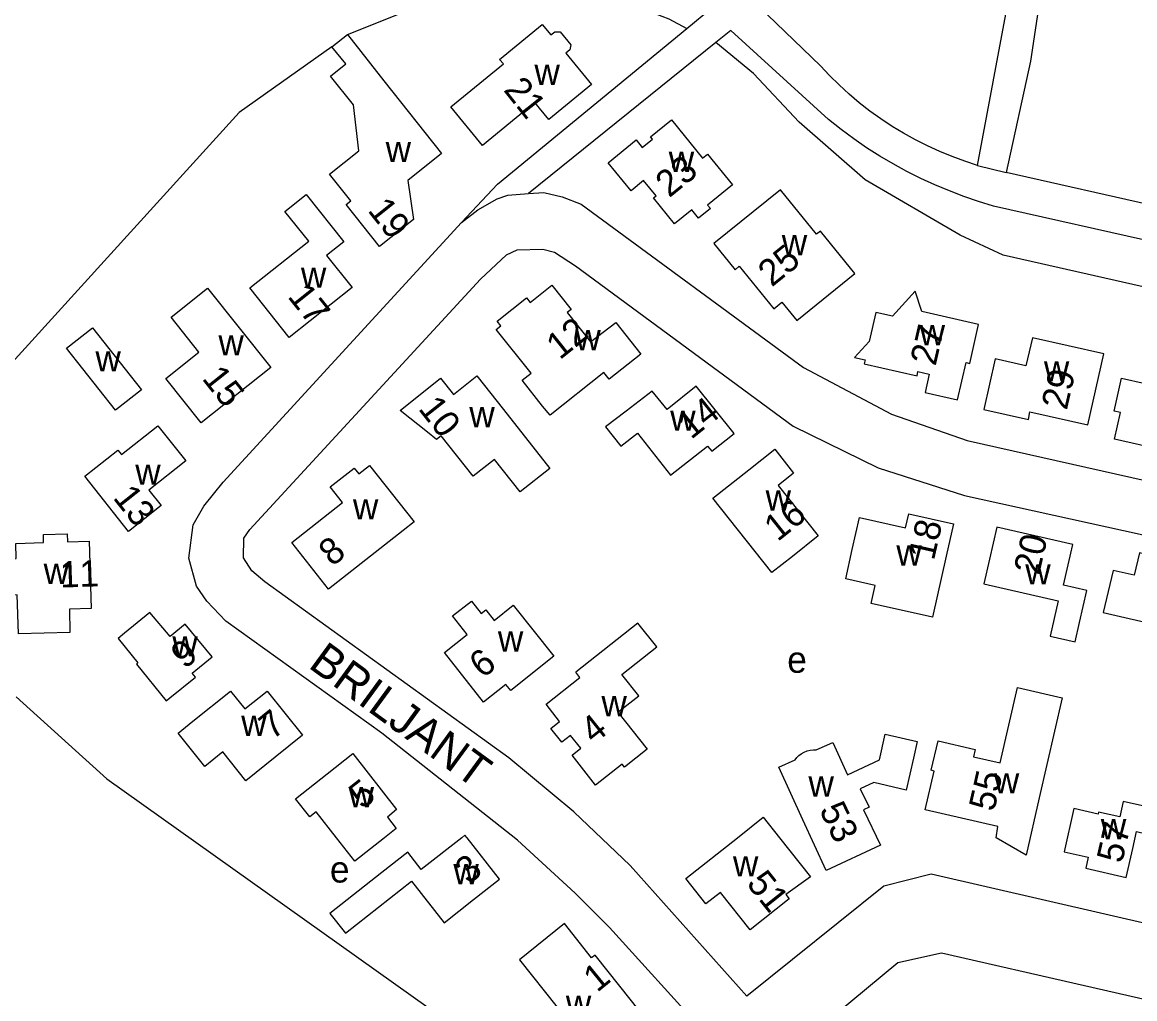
# Model space of a CAD drawing. Extents: x 159441 to 162086, y 388175 to 389787.
# Drawn here: x 160042 to 160211, y 388725.5 to 388873.9 of the extents above; entities that cross this region are included whole.
import ezdxf

# ---------------------------------------------------------------- set-up
doc = ezdxf.new("R2010")
doc.units = 0
for name, color, linetype in [('BLT_Basislijn', 7, 'Continuous'), ('BLT_Bebouwing', 7, 'Continuous'), ('BLT_Centroide', 7, 'Continuous'), ('BLT_Huisnummer', 7, 'Continuous'), ('BLT_Straatnaam', 7, 'Continuous')]:
    doc.layers.add(name, color=color, linetype=linetype)

msp = doc.modelspace()

# ---------------------------------------------------------------- linework, layer by layer
at = {"layer": 'BLT_Basislijn'}
for p, q in [((160163.23, 388867.23), (160150.84, 388879.16)), ((160187.09, 388852.12), (160191.81, 388877.57)), ((160142.94, 388872.91), (160146.74, 388876.03)), ((160149.61, 388872.62), (160147.33, 388870.78)), ((160164.44, 388859.07), (160149.61, 388872.62)), ((160147.33, 388870.78), (160118.89, 388847.84)), ((160187.09, 388852.12), (160191.44, 388851.02)), ((160360.88, 388812.74), (160191.44, 388851.02)), ((160346.93, 388810.56), (160189.5, 388845.95)), ((160115.55, 388838.53), (160117.14, 388839.28)), ((160117.14, 388839.28), (160121.07, 388839.39)), ((160121.07, 388839.39), (160122.81, 388838.92)), ((160111.6, 388834.85), (160115.55, 388838.53)), ((160122.81, 388838.92), (160125.99, 388836.85)), ((160125.99, 388836.85), (160159.06, 388812.49)), ((160076.55, 388796.83), (160111.6, 388834.85)), ((160159.06, 388812.49), (160171.97, 388806.18)), ((160171.97, 388806.18), (160185.1, 388801.99)), ((160185.1, 388801.99), (160246.65, 388788.38)), ((160075.64, 388795.49), (160076.55, 388796.83)), ((160075.56, 388792.53), (160075.64, 388795.49)), ((160076.87, 388790.53), (160075.56, 388792.53)), ((160078.84, 388788.84), (160076.87, 388790.53)), ((160115.87, 388762.13), (160078.84, 388788.84)), ((160125.73, 388753.92), (160115.87, 388762.13)), ((160134.33, 388745.8), (160125.73, 388753.92)), ((160152.02, 388725.93), (160134.33, 388745.8)), ((160180.01, 388744.45), (160172.85, 388742.62)), ((160234.52, 388731.91), (160180.01, 388744.45)), ((160172.85, 388742.62), (160152.02, 388725.93))]:
    msp.add_line(p, q, dxfattribs=at)
for points in [[(160218.9, 388909.49), (160213.34, 388904.91), (160206.65, 388898.54), (160202.29, 388892.55), (160198.36, 388884.11), (160196.72, 388878.8), (160195.13, 388867.95), (160191.44, 388851.02)], [(160091.36, 388872), (160103.18, 388876.69), (160111.74, 388878.51), (160119, 388879.07), (160125.96, 388878.73), (160132.75, 388877.29), (160140.2, 388874.39), (160142.94, 388872.91)], [(160108.7, 388843.42), (160114.14, 388849.26), (160142.94, 388872.91)], [(160089.02, 388870.15), (160074.94, 388860.17), (160014.9, 388794.07)], [(160345.36, 388803.54), (160190.94, 388838.49), (160184.45, 388841.51), (160169.98, 388849.95), (160159.97, 388858.67), (160153.03, 388866.08), (160147.33, 388870.78)], [(160187.09, 388852.12), (160185.14, 388852.75), (160183.22, 388853.45), (160181.33, 388854.23), (160179.46, 388855.08), (160177.64, 388856), (160175.85, 388856.99), (160174.1, 388858.05), (160172.39, 388859.18), (160170.73, 388860.38), (160169.11, 388861.64), (160167.55, 388862.96), (160166.04, 388864.35), (160164.58, 388865.79), (160163.23, 388867.23)], [(160189.5, 388845.95), (160187.24, 388846.64), (160185, 388847.41), (160182.79, 388848.25), (160180.61, 388849.16), (160178.46, 388850.15), (160176.34, 388851.21), (160174.26, 388852.34), (160172.22, 388853.54), (160170.23, 388854.81), (160168.27, 388856.15), (160166.37, 388857.55), (160164.44, 388859.07)], [(160108.7, 388843.42), (160111.15, 388845.37), (160114.12, 388847.06), (160115.71, 388847.62), (160118.89, 388847.84)], [(160118.89, 388847.84), (160121.21, 388847.99), (160123.99, 388847.35), (160126.85, 388846.24), (160160.65, 388821.41), (160174.02, 388814.31), (160185.49, 388810.35), (160339.15, 388775.78)], [(160128.08, 388707.15), (160129.69, 388708.17), (160145.39, 388720.67), (160131.15, 388736.37), (160125.98, 388741.58), (160117.21, 388749.62), (160096.61, 388765.86), (160072.89, 388782.89), (160069.99, 388785.94), (160068.43, 388788.2), (160067.27, 388792.47), (160067.96, 388797.53), (160069.56, 388800.35), (160072.51, 388804), (160108.7, 388843.42)], [(160041.05, 388771.4), (160054.83, 388758.93), (160120.14, 388712.44), (160128.08, 388707.15)], [(160114.51, 388683.05), (160165.44, 388723.15), (160174.96, 388731.02), (160181.6, 388732.52), (160225.05, 388722.57), (160225.4, 388722.49)]]:
    msp.add_lwpolyline(points, dxfattribs=at)
at = {"layer": 'BLT_Bebouwing'}
for p, q in [((160089.02, 388870.15), (160091.36, 388872)), ((160091.36, 388872), (160096.91, 388864.98)), ((160135.49, 388782.6), (160126.07, 388775.13)), ((160138.36, 388778.98), (160135.49, 388782.6)), ((160133.06, 388774.77), (160138.36, 388778.98)), ((160135.61, 388771.56), (160133.06, 388774.77)), ((160132.43, 388769.05), (160135.61, 388771.56))]:
    msp.add_line(p, q, dxfattribs=at)
for points in [[(160120.97, 388873.54), (160122.28, 388871.93), (160122.89, 388872.43), (160123.66, 388872.41), (160125.29, 388870.43), (160125.15, 388869.67), (160124.54, 388869.17), (160128.46, 388864.39), (160121.95, 388859.1), (160119.85, 388861.69), (160111.9, 388855.13), (160107.09, 388861), (160115.05, 388867.53), (160114.48, 388868.22), (160120.97, 388873.54)], [(160096.91, 388864.98), (160105.67, 388853.9), (160100.52, 388849.8), (160101.39, 388843.9), (160096.23, 388839.82), (160091.17, 388846.2), (160091.87, 388846.75), (160088.66, 388850.79), (160093.11, 388854.31), (160092.27, 388861.3), (160088.8, 388865.69), (160091.11, 388867.52), (160089.02, 388870.15)], [(160135.22, 388855.98), (160136.14, 388854.84), (160137.7, 388856.1), (160137.41, 388856.45), (160140.57, 388859.02), (160145.29, 388853.22), (160146.04, 388853.83), (160149.86, 388849.16), (160146.07, 388846.07), (160146.49, 388845.56), (160144.71, 388844.11), (160143.67, 388845.38), (160141.06, 388843.25), (160137.88, 388847.17), (160138.27, 388847.49), (160136.36, 388849.83), (160134.46, 388848.26), (160130.96, 388852.51), (160135.22, 388855.98)], [(160085.1, 388847.69), (160090.8, 388840.49), (160088.21, 388838.43), (160092.07, 388833.57), (160082.5, 388825.99), (160076.54, 388833.52), (160085.48, 388840.6), (160081.88, 388845.14), (160085.1, 388847.69)], [(160147.04, 388840.24), (160150.26, 388836.28), (160150.89, 388836.79), (160156.12, 388830.33), (160157.37, 388831.34), (160159.61, 388828.55), (160168.45, 388835.71), (160163.23, 388842.15), (160162.61, 388841.65), (160157.13, 388848.41), (160147.04, 388840.24)], [(160131.13, 388819.64), (160130.3, 388820.68), (160122.15, 388814.16), (160121.02, 388815.57), (160117.9, 388819.48), (160119.27, 388820.58), (160113.98, 388827.19), (160114.68, 388827.74), (160114.12, 388828.44), (160118.59, 388831.99), (160119.14, 388831.3), (160122.4, 388833.92), (160125.33, 388830.23), (160124.74, 388829.75), (160128.28, 388825.3), (160132.11, 388828.28), (160135.92, 388823.47), (160131.13, 388819.64)], [(160070.13, 388833.46), (160079.73, 388821.42), (160069.17, 388813.01), (160063.81, 388819.74), (160068.82, 388823.73), (160064.58, 388829.05), (160070.13, 388833.46)], [(160170, 388822.59), (160169.86, 388821.99), (160177.88, 388820.16), (160178.02, 388820.79), (160179.74, 388820.41), (160179.13, 388817.63), (160184.04, 388816.52), (160185.34, 388822.18), (160185.88, 388822.05), (160187.2, 388827.94), (160178.61, 388829.91), (160177.62, 388833.01), (160174.17, 388829.2), (160171.63, 388829.77), (160170.63, 388825.38), (160168.38, 388822.95), (160170, 388822.59)], [(160194.8, 388813.52), (160195.03, 388814.71), (160203.8, 388812.71), (160206.25, 388823.5), (160195.4, 388825.93), (160194.43, 388821.66), (160189.77, 388822.72), (160188.04, 388815.05), (160194.8, 388813.52)], [(160223.52, 388806.98), (160207.88, 388810.55), (160208.78, 388814.59), (160207.81, 388814.8), (160208.92, 388819.79), (160216.14, 388818.18), (160217.77, 388825.31), (160227.21, 388823.15), (160223.52, 388806.98)], [(160111.01, 388820.16), (160115.05, 388815.03), (160122.12, 388806.1), (160117.6, 388802.52), (160113.7, 388807.45), (160110.48, 388804.9), (160105.6, 388811.04), (160104.91, 388810.49), (160103.51, 388811.6), (160099.37, 388814.9), (160105.51, 388819.8), (160107.5, 388817.34), (160111.01, 388820.16)], [(160146.7, 388808.7), (160150.09, 388811.37), (160144.33, 388818.56), (160139.91, 388815.03), (160137.63, 388817.85), (160133.68, 388814.79), (160130.58, 388812.4), (160132.9, 388809.46), (160135.43, 388811.46), (160140.46, 388805.07), (160146.07, 388809.49), (160146.7, 388808.7)], [(160051.48, 388804.89), (160056.51, 388808.87), (160057.03, 388808.2), (160062.57, 388812.58), (160066.8, 388807.23), (160061.21, 388802.81), (160063.07, 388800.46), (160058.1, 388796.53), (160051.48, 388804.89)], [(160158.96, 388792.73), (160155.84, 388790.26), (160146.86, 388801.56), (160152.35, 388805.9), (160156.27, 388809), (160159.14, 388805.36), (160156.8, 388803.49), (160162.89, 388795.83), (160158.96, 388792.73)], [(160088.51, 388787.77), (160082.93, 388794.82), (160090.63, 388800.93), (160088.76, 388803.29), (160092.38, 388806.14), (160093.08, 388805.25), (160094.73, 388806.55), (160101.48, 388797.99), (160099.83, 388796.68), (160088.51, 388787.77)], [(160182.31, 388792.78), (160180.21, 388783.48), (160170.92, 388785.58), (160171.54, 388788.32), (160167.05, 388789.34), (160168.05, 388793.77), (160169.15, 388798.65), (160176.11, 388797.07), (160176.62, 388799.21), (160183.42, 388797.65), (160182.31, 388792.78)], [(160202.56, 388782.68), (160203.67, 388787.55), (160200.14, 388788.34), (160201.56, 388794.54), (160190.01, 388797.17), (160188.9, 388792.31), (160188.04, 388788.56), (160199.34, 388785.97), (160198.11, 388780.6), (160201.89, 388779.74), (160202.56, 388782.68)], [(160048.83, 388794.94), (160052.12, 388795.03), (160052.43, 388784.82), (160049.15, 388784.71), (160049.22, 388781.15), (160041.4, 388780.96), (160041.23, 388786.91), (160039.62, 388786.86), (160038.02, 388789.56), (160039.46, 388792.37), (160041.07, 388792.41), (160041.01, 388794.71), (160045.22, 388794.83), (160045.18, 388796.03), (160048.8, 388796.14), (160048.83, 388794.94)], [(160223.08, 388782.73), (160224.18, 388787.61), (160220.78, 388788.38), (160221.15, 388790.08), (160216.23, 388791.23), (160216.39, 388792.16), (160211.65, 388793.28), (160210.87, 388789.87), (160207.65, 388790.61), (160206.17, 388784.19), (160215.17, 388782.14), (160214.96, 388781.22), (160218.67, 388780.38), (160218.45, 388779.41), (160222.14, 388778.58), (160223.08, 388782.73)], [(160115.45, 388773.28), (160112.04, 388770.59), (160106.09, 388778.11), (160109.57, 388780.89), (160107.33, 388783.69), (160110.19, 388785.95), (160111.67, 388784.06), (160112.38, 388784.62), (160113.66, 388783.01), (160116.54, 388785.31), (160122.7, 388777.59), (160116.17, 388772.38), (160115.45, 388773.28)], [(160064.39, 388771.23), (160068.27, 388774.39), (160067.78, 388774.99), (160070.81, 388777.46), (160066.73, 388782.42), (160064.43, 388780.55), (160061.37, 388784.23), (160057.5, 388781.07), (160056.52, 388780.27), (160059.54, 388776.56), (160059.31, 388776.37), (160063.86, 388770.8), (160064.39, 388771.23)], [(160136.89, 388763.43), (160133.45, 388760.7), (160133.08, 388761.17), (160129.07, 388757.99), (160125.5, 388762.55), (160126.82, 388763.58), (160125.24, 388765.54), (160123.92, 388764.51), (160122.24, 388766.6), (160123.59, 388767.67), (160121.53, 388770.27), (160126.69, 388774.35), (160126.07, 388775.13)], [(160084.54, 388765.55), (160080.39, 388762.23), (160075.94, 388758.66), (160072.45, 388763.02), (160069.73, 388760.84), (160065.68, 388765.9), (160067.89, 388767.69), (160073.59, 388772.27), (160075.78, 388769.58), (160079.2, 388772.27), (160084.54, 388765.55)], [(160196.45, 388756.04), (160194.45, 388747.37), (160189.9, 388750), (160190.16, 388751.71), (160179.14, 388754.23), (160180.46, 388760.11), (160180.05, 388760.24), (160181.08, 388764.7), (160186.72, 388763.4), (160186.46, 388762.28), (160190.51, 388761.35), (160193.14, 388772.82), (160199.95, 388771.25), (160196.45, 388756.04)], [(160132.43, 388769.05), (160136.89, 388763.43)], [(160164.1, 388745.03), (160160.56, 388752.7), (160156.88, 388760.69), (160159.37, 388761.85), (160159.63, 388762.17), (160159.93, 388762.47), (160160.29, 388762.75), (160160.74, 388763.01), (160161.21, 388763.19), (160161.66, 388763.3), (160162.16, 388763.34), (160162.57, 388763.33), (160165.07, 388764.48), (160167.34, 388759.57), (160172.16, 388761.83), (160173.06, 388765.73), (160177.92, 388764.61), (160177.34, 388762.07), (160176.21, 388757.2), (160171.34, 388758.38), (160169.27, 388757.41), (160170.6, 388754.65), (160169.75, 388754.24), (160172.35, 388748.89), (160164.1, 388745.03)], [(160096.98, 388750), (160094.86, 388748.32), (160092.5, 388746.46), (160089.7, 388750), (160086.6, 388753.93), (160085.66, 388753.18), (160083.5, 388755.92), (160088.28, 388759.7), (160092.21, 388762.8), (160098.84, 388754.27), (160097.43, 388753.12), (160098.78, 388751.42), (160096.98, 388750)], [(160215.04, 388754.16), (160209.21, 388755.5), (160208.68, 388753.17), (160205.47, 388753.9), (160205.4, 388753.59), (160201.71, 388754.43), (160200.21, 388747.86), (160203.9, 388747.02), (160203.52, 388745.37), (160209.67, 388743.98), (160210.66, 388748.37), (160211.24, 388750.93), (160214.17, 388750.24), (160215.04, 388754.16)], [(160156.98, 388750), (160161.68, 388744.06), (160157.95, 388741.39), (160158.45, 388740.72), (160152.55, 388736.02), (160148.01, 388741.69), (160145.82, 388739.97), (160142.78, 388743.82), (160150.59, 388750), (160154.52, 388753.11), (160156.98, 388750)], [(160110.53, 388740.62), (160114.46, 388743.71), (160109.53, 388750), (160109.22, 388750.39), (160108.72, 388750), (160102.56, 388745.18), (160100.53, 388747.81), (160096.6, 388744.72), (160088.7, 388738.5), (160091.07, 388735.5), (160101.09, 388743.39), (160106.04, 388737.09), (160110.53, 388740.62)], [(160128.07, 388716.58), (160133.12, 388720.58), (160136.22, 388723.05), (160134.52, 388725.21), (160129.01, 388732.15), (160128.46, 388731.75), (160124.34, 388736.96), (160117.49, 388731.46), (160123.24, 388724.24), (160121.07, 388722.53), (160123.76, 388719.14), (160125.15, 388720.24), (160128.07, 388716.58)]]:
    msp.add_lwpolyline(points, dxfattribs=at)
msp.add_lwpolyline([(160052.63, 388827.44), (160060.07, 388818.03), (160056.15, 388814.93), (160048.7, 388824.34)], close=True, dxfattribs=at)

# ---------------------------------------------------------------- texts
at = {"layer": 'BLT_Centroide'}
for s, p in [('w', (160119.77, 388864.34)), ('w', (160097.17, 388852.62)), ('w', (160140.17, 388851.12)), ('w', (160157.34, 388838.47)), ('w', (160084.3, 388833.53)), ('w', (160178.27, 388824.78)), ('w', (160071.77, 388823.25)), ('w', (160125.98, 388824.03)), ('w', (160053.09, 388820.82)), ('w', (160197.15, 388819.31)), ('w', (160109.88, 388812.34)), ('w', (160140.39, 388811.81)), ('w', (160059.14, 388803.61)), ('w', (160154.88, 388799.69)), ('w', (160092.2, 388798.34)), ('w', (160174.74, 388791.34)), ('w', (160045.22, 388788.55)), ('w', (160194.32, 388788.47)), ('w', (160064.77, 388777.53)), ('w', (160114.22, 388778.28)), ('e', (160158.17, 388775.05)), ('w', (160129.95, 388768.45)), ('w', (160075.23, 388765.47)), ('w', (160189.55, 388756.72)), ('w', (160161.39, 388756.23)), ('w', (160091.54, 388754.62)), ('w', (160205.8, 388749.75)), ('e', (160088.71, 388743.19)), ('w', (160107.46, 388742.94)), ('w', (160149.92, 388744.12)), ('w', (160124.54, 388722.95))]:
    msp.add_text(s, height=4, dxfattribs=at).set_placement(p)
at = {"layer": 'BLT_Huisnummer'}
for s, rotation, p in [('21', 308.5267, (160114.97, 388863.54)), ('23', 39.1153, (160140.24, 388847.11)), ('19', 308.5267, (160094.33, 388845.25)), ('25', 39.015, (160155.81, 388833.55)), ('17', 308.5267, (160082.17, 388832.17)), ('12', 38.5008, (160123.61, 388822.49)), ('27', 77.0623, (160180.69, 388821.54)), ('15', 308.5267, (160069.16, 388819.72)), ('29', 77.1478, (160200.62, 388814.83)), ('10', 308.2228, (160102.02, 388815.14)), ('14', 38.5008, (160143.56, 388810.4)), ('13', 308.3527, (160055.64, 388801.61)), ('16', 38.5008, (160156.7, 388794.88)), ('18', 77.2336, (160180.44, 388791.99)), ('8', 38.6598, (160089.05, 388791.09)), ('20', 77.2336, (160196.42, 388789.78)), ('11', 1.8847, (160047.75, 388787.99)), ('9', 39.1955, (160066.65, 388775.51)), ('6', 38.6598, (160111.92, 388774.09)), ('7', 38.6851, (160079.98, 388764.76)), ('4', 38.6598, (160128.8, 388764.12)), ('55', 77.2138, (160189.59, 388753.86)), ('5', 38.2867, (160093.62, 388754.21)), ('53', 295.5803, (160162.97, 388754.26)), ('57', 77.2138, (160209.01, 388745.98)), ('3', 38.1926, (160109.78, 388742.83)), ('51', 308.5575, (160151.85, 388743)), ('1', 39.134, (160129.28, 388726.4))]:
    msp.add_text(s, height=4, rotation=rotation, dxfattribs=at).set_placement(p)
at = {"layer": 'BLT_Straatnaam'}
msp.add_text('BRILJANT', height=5, rotation=323.8396, dxfattribs=at).set_placement((160085.26, 388775.95))

doc.saveas('drawing.dxf')
